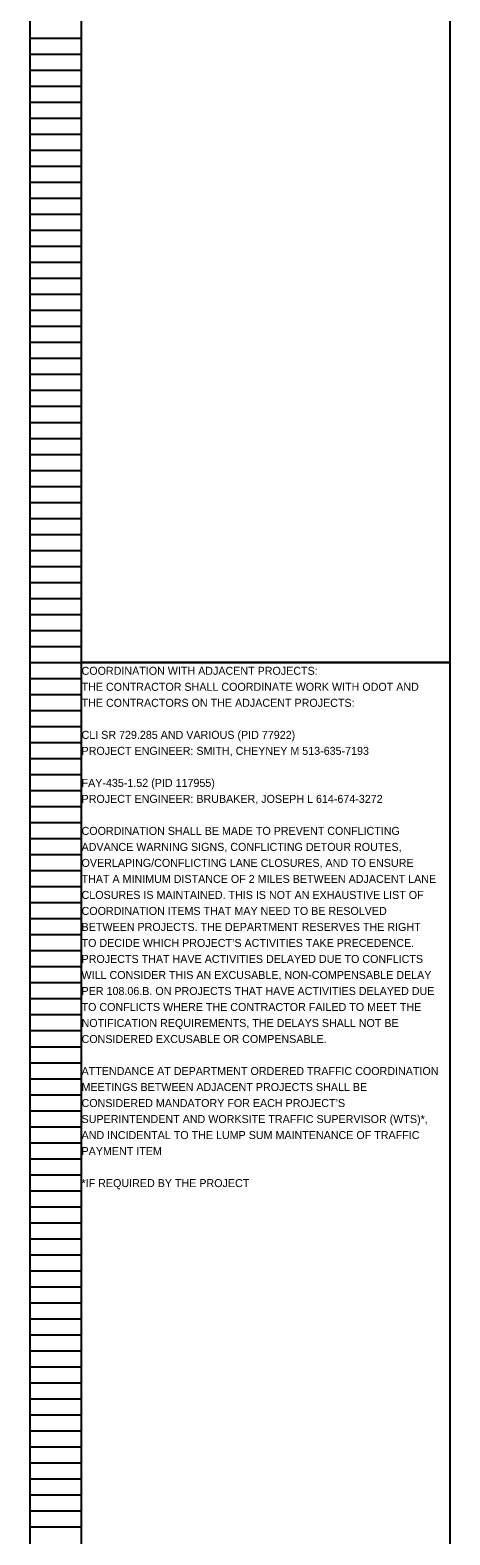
# Model space of a CAD drawing. Extents: x 16463 to 16500, y 5400 to 5823.
# Drawn here: x 16463.05 to 16470.39, y 5505.81 to 5532.13 of the extents above; entities that cross this region are included whole.
import ezdxf

# ---------------------------------------------------------------- set-up
doc = ezdxf.new("R2010")
doc.units = 0
for name, color, linetype in [('SC_Scratch1', 7, 'Continuous'), ('SH_Data', 7, 'Continuous'), ('SH_Text', 7, 'Continuous')]:
    doc.layers.add(name, color=color, linetype=linetype)

msp = doc.modelspace()

# ---------------------------------------------------------------- linework, layer by layer
at = {"layer": 'SC_Scratch1'}
for points in [[(16463.949, 5541.232), (16470.389, 5541.232), (16470.389, 5521.072), (16463.949, 5521.072)], [(16463.949, 5521.072), (16470.389, 5521.072), (16470.389, 5500.912), (16463.949, 5500.912)]]:
    msp.add_lwpolyline(points, close=True, dxfattribs=at)
at = {"layer": 'SH_Data'}
for p, q in [((16463.049, 5521.072), (16463.049, 5541.232)), ((16463.949, 5521.072), (16463.949, 5541.232)), ((16463.049, 5531.992), (16463.949, 5531.992)), ((16463.049, 5531.712), (16463.949, 5531.712)), ((16463.049, 5531.432), (16463.949, 5531.432)), ((16463.049, 5531.152), (16463.949, 5531.152)), ((16463.049, 5530.872), (16463.949, 5530.872)), ((16463.049, 5530.592), (16463.949, 5530.592)), ((16463.049, 5530.312), (16463.949, 5530.312)), ((16463.049, 5530.032), (16463.949, 5530.032)), ((16463.049, 5529.752), (16463.949, 5529.752)), ((16463.049, 5529.472), (16463.949, 5529.472)), ((16463.049, 5529.192), (16463.949, 5529.192)), ((16463.049, 5528.912), (16463.949, 5528.912)), ((16463.049, 5528.632), (16463.949, 5528.632)), ((16463.049, 5528.352), (16463.949, 5528.352)), ((16463.049, 5528.072), (16463.949, 5528.072)), ((16463.049, 5527.792), (16463.949, 5527.792)), ((16463.049, 5527.512), (16463.949, 5527.512)), ((16463.049, 5527.232), (16463.949, 5527.232)), ((16463.049, 5526.952), (16463.949, 5526.952)), ((16463.049, 5526.672), (16463.949, 5526.672)), ((16463.049, 5526.392), (16463.949, 5526.392)), ((16463.049, 5526.112), (16463.949, 5526.112)), ((16463.049, 5525.832), (16463.949, 5525.832)), ((16463.049, 5525.552), (16463.949, 5525.552)), ((16463.049, 5525.272), (16463.949, 5525.272)), ((16463.049, 5524.992), (16463.949, 5524.992)), ((16463.049, 5524.712), (16463.949, 5524.712)), ((16463.049, 5524.432), (16463.949, 5524.432)), ((16463.049, 5524.152), (16463.949, 5524.152)), ((16463.049, 5523.872), (16463.949, 5523.872)), ((16463.049, 5523.592), (16463.949, 5523.592)), ((16463.049, 5523.312), (16463.949, 5523.312)), ((16463.049, 5523.032), (16463.949, 5523.032)), ((16463.049, 5522.752), (16463.949, 5522.752)), ((16463.049, 5522.472), (16463.949, 5522.472)), ((16463.049, 5522.192), (16463.949, 5522.192)), ((16463.049, 5521.912), (16463.949, 5521.912)), ((16463.049, 5521.632), (16463.949, 5521.632)), ((16463.049, 5521.352), (16463.949, 5521.352)), ((16463.049, 5500.912), (16463.049, 5521.072)), ((16463.049, 5521.072), (16463.949, 5521.072)), ((16463.049, 5521.072), (16463.949, 5521.072)), ((16463.949, 5500.912), (16463.949, 5521.072)), ((16463.049, 5520.792), (16463.949, 5520.792)), ((16463.049, 5520.512), (16463.949, 5520.512)), ((16463.049, 5520.232), (16463.949, 5520.232)), ((16463.049, 5519.952), (16463.949, 5519.952)), ((16463.049, 5519.672), (16463.949, 5519.672)), ((16463.049, 5519.392), (16463.949, 5519.392)), ((16463.049, 5519.112), (16463.949, 5519.112)), ((16463.049, 5518.832), (16463.949, 5518.832)), ((16463.049, 5518.552), (16463.949, 5518.552)), ((16463.049, 5518.272), (16463.949, 5518.272)), ((16463.049, 5517.992), (16463.949, 5517.992)), ((16463.049, 5517.712), (16463.949, 5517.712)), ((16463.049, 5517.432), (16463.949, 5517.432)), ((16463.049, 5517.152), (16463.949, 5517.152)), ((16463.049, 5516.872), (16463.949, 5516.872)), ((16463.049, 5516.592), (16463.949, 5516.592)), ((16463.049, 5516.312), (16463.949, 5516.312)), ((16463.049, 5516.032), (16463.949, 5516.032)), ((16463.049, 5515.752), (16463.949, 5515.752)), ((16463.049, 5515.472), (16463.949, 5515.472)), ((16463.049, 5515.192), (16463.949, 5515.192)), ((16463.049, 5514.912), (16463.949, 5514.912)), ((16463.049, 5514.632), (16463.949, 5514.632)), ((16463.049, 5514.352), (16463.949, 5514.352)), ((16463.049, 5514.072), (16463.949, 5514.072)), ((16463.049, 5513.792), (16463.949, 5513.792)), ((16463.049, 5513.512), (16463.949, 5513.512)), ((16463.049, 5513.232), (16463.949, 5513.232)), ((16463.049, 5512.952), (16463.949, 5512.952)), ((16463.049, 5512.672), (16463.949, 5512.672)), ((16463.049, 5512.392), (16463.949, 5512.392)), ((16463.049, 5512.112), (16463.949, 5512.112)), ((16463.049, 5511.832), (16463.949, 5511.832)), ((16463.049, 5511.552), (16463.949, 5511.552)), ((16463.049, 5511.272), (16463.949, 5511.272)), ((16463.049, 5510.992), (16463.949, 5510.992)), ((16463.049, 5510.712), (16463.949, 5510.712)), ((16463.049, 5510.432), (16463.949, 5510.432)), ((16463.049, 5510.152), (16463.949, 5510.152)), ((16463.049, 5509.872), (16463.949, 5509.872)), ((16463.049, 5509.592), (16463.949, 5509.592)), ((16463.049, 5509.312), (16463.949, 5509.312)), ((16463.049, 5509.032), (16463.949, 5509.032)), ((16463.049, 5508.752), (16463.949, 5508.752)), ((16463.049, 5508.472), (16463.949, 5508.472)), ((16463.049, 5508.192), (16463.949, 5508.192)), ((16463.049, 5507.912), (16463.949, 5507.912)), ((16463.049, 5507.632), (16463.949, 5507.632)), ((16463.049, 5507.352), (16463.949, 5507.352)), ((16463.049, 5507.072), (16463.949, 5507.072)), ((16463.049, 5506.792), (16463.949, 5506.792)), ((16463.049, 5506.512), (16463.949, 5506.512)), ((16463.049, 5506.232), (16463.949, 5506.232)), ((16463.049, 5505.952), (16463.949, 5505.952))]:
    msp.add_line(p, q, dxfattribs=at)

# ---------------------------------------------------------------- texts
at = {"layer": 'SH_Text'}
for s, p in [('COORDINATION WITH ADJACENT PROJECTS:', (16463.949, 5520.856)), ('THE CONTRACTOR SHALL COORDINATE WORK WITH ODOT AND ', (16463.949, 5520.576)), ('THE CONTRACTORS ON THE ADJACENT PROJECTS: ', (16463.949, 5520.296)), ('CLI SR 729.285 AND VARIOUS (PID 77922) ', (16463.949, 5519.736)), ('PROJECT ENGINEER: SMITH, CHEYNEY M 513-635-7193', (16463.949, 5519.456)), ('FAY-435-1.52 (PID 117955)', (16463.949, 5518.896)), ('PROJECT ENGINEER: BRUBAKER, JOSEPH L 614-674-3272', (16463.949, 5518.616)), ('COORDINATION SHALL BE MADE TO PREVENT CONFLICTING ', (16463.949, 5518.056)), ('ADVANCE WARNING SIGNS, CONFLICTING DETOUR ROUTES, ', (16463.949, 5517.776)), ('OVERLAPING/CONFLICTING LANE CLOSURES, AND TO ENSURE ', (16463.949, 5517.496)), ('THAT A MINIMUM DISTANCE OF 2 MILES BETWEEN ADJACENT LANE ', (16463.949, 5517.216)), ('CLOSURES IS MAINTAINED. THIS IS NOT AN EXHAUSTIVE LIST OF ', (16463.949, 5516.936)), ('COORDINATION ITEMS THAT MAY NEED TO BE RESOLVED ', (16463.949, 5516.656)), ('BETWEEN PROJECTS. THE DEPARTMENT RESERVES THE RIGHT ', (16463.949, 5516.376)), ('TO DECIDE WHICH PROJECT’S ACTIVITIES TAKE PRECEDENCE. ', (16463.949, 5516.096)), ('PROJECTS THAT HAVE ACTIVITIES DELAYED DUE TO CONFLICTS ', (16463.949, 5515.816)), ('WILL CONSIDER THIS AN EXCUSABLE, NON-COMPENSABLE DELAY ', (16463.949, 5515.536)), ('PER 108.06.B. ON PROJECTS THAT HAVE ACTIVITIES DELAYED DUE ', (16463.949, 5515.256)), ('TO CONFLICTS WHERE THE CONTRACTOR FAILED TO MEET THE ', (16463.949, 5514.976)), ('NOTIFICATION REQUIREMENTS, THE DELAYS SHALL NOT BE ', (16463.949, 5514.696)), ('CONSIDERED EXCUSABLE OR COMPENSABLE.', (16463.949, 5514.416)), ('ATTENDANCE AT DEPARTMENT ORDERED TRAFFIC COORDINATION ', (16463.949, 5513.856)), ('MEETINGS BETWEEN ADJACENT PROJECTS SHALL BE ', (16463.949, 5513.576)), ('CONSIDERED MANDATORY FOR EACH PROJECT’S ', (16463.949, 5513.296)), ('SUPERINTENDENT AND WORKSITE TRAFFIC SUPERVISOR (WTS)*, ', (16463.949, 5513.016)), ('AND INCIDENTAL TO THE LUMP SUM MAINTENANCE OF TRAFFIC ', (16463.949, 5512.736)), ('PAYMENT ITEM', (16463.949, 5512.456)), ('*IF REQUIRED BY THE PROJECT', (16463.949, 5511.896))]:
    msp.add_text(s, height=0.14, dxfattribs=at).set_placement(p)

doc.saveas('drawing.dxf')
